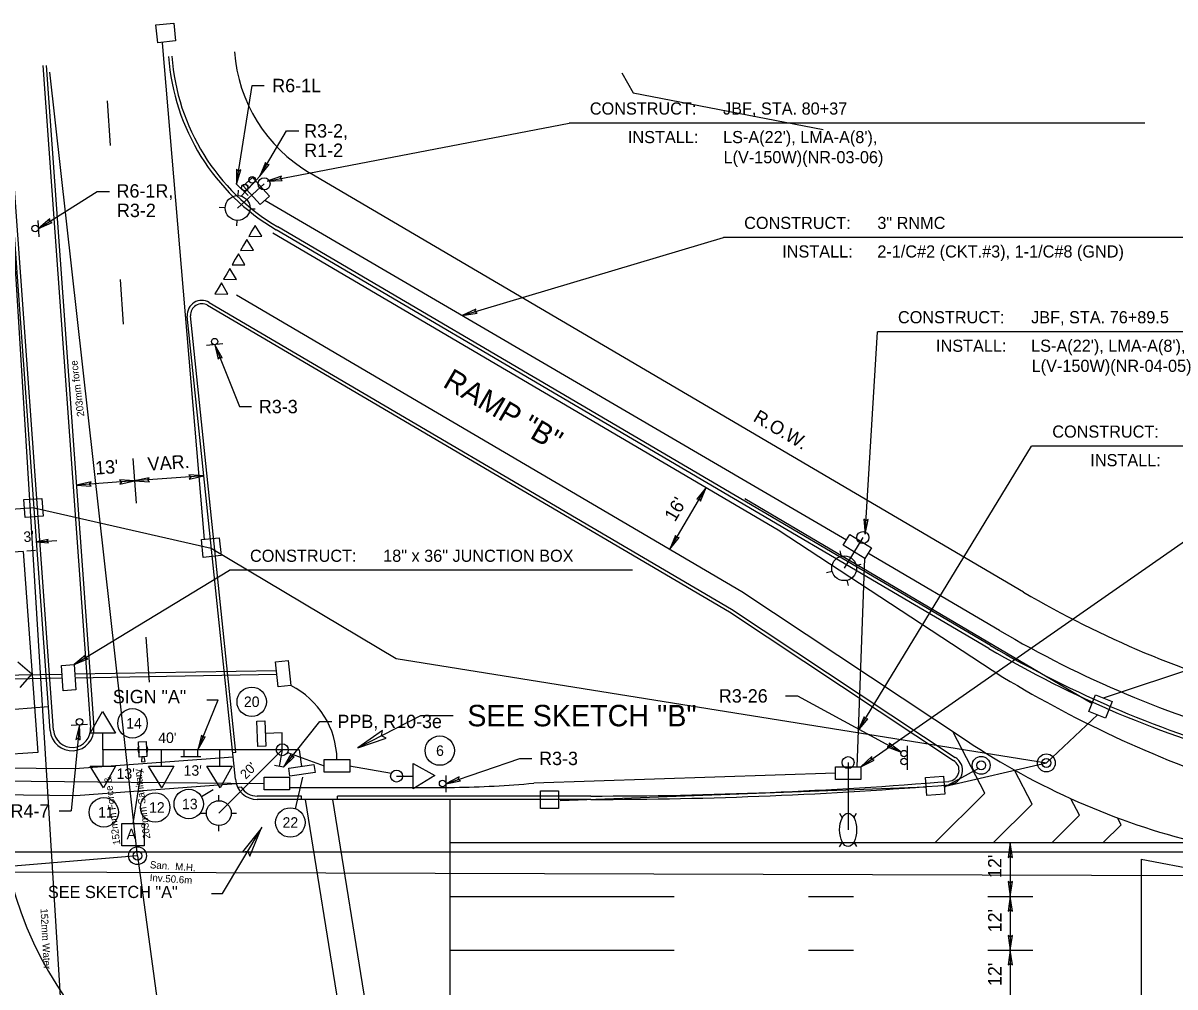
# Model space of a CAD drawing. Extents: x 488740 to 507913, y 466518 to 497949.
# Drawn here: x 503498.7 to 503756.2, y 496091.2 to 496306.6 of the extents above; entities that cross this region are included whole.
import ezdxf

# ---------------------------------------------------------------- set-up
doc = ezdxf.new("R2010")
doc.units = 0
for name, color, linetype in [('1', 7, 'Continuous'), ('10', 7, 'Continuous'), ('12', 7, 'Continuous'), ('23', 7, 'Continuous'), ('32', 7, 'Continuous'), ('36', 7, 'Continuous'), ('38', 7, 'Continuous'), ('42', 7, 'Continuous'), ('6', 7, 'Continuous'), ('8', 7, 'Continuous')]:
    doc.layers.add(name, color=color, linetype=linetype)

msp = doc.modelspace()

# ---------------------------------------------------------------- linework, layer by layer
at = {"layer": '1'}
for p, q in [((503505.55, 496148.6), (503494.86, 496296.48)), ((503503.13, 496297.07), (503513.82, 496149.2)), ((503503.88, 496297.13), (503514.57, 496149.25)), ((503504.8, 496148.54), (503494.11, 496296.42)), ((503722.34, 496179.43), (503562.78, 496273.13)), ((503714.59, 496166.85), (503555.3, 496260.39)), ((503714.97, 496167.5), (503555.68, 496261.04)), ((503539.97, 496243.53), (503656.64, 496175.01)), ((503540.35, 496244.17), (503657.04, 496175.65)), ((503546.19, 496137.67), (503535.44, 496241.12)), ((503546.32, 496143.64), (503536.18, 496241.2)), ((503657.04, 496175.65), (503707.08, 496142.47)), ((503656.64, 496175.01), (503706.67, 496141.85)), ((503546.32, 496143.64), (503545.57, 496143.56)), ((503547.52, 496135.89), (503546.71, 496135.8)), ((503560.96, 496133.88), (503551.07, 496133.88)), ((503625.63, 496133.12), (503551.07, 496133.12)), ((503560.96, 496133.08), (503560.96, 496133.88)), ((503568.97, 496133.08), (503568.97, 496133.88)), ((503625.63, 496133.88), (503568.97, 496133.88))]:
    msp.add_line(p, q, dxfattribs=at)
for points in [[(503528.44, 496306.17), (503532.42, 496306.58), (503532.84, 496302.6), (503528.86, 496302.19)], [(503498.92, 496200.1), (503502.92, 496200.39), (503503.2, 496196.4), (503499.21, 496196.11)], [(503538.6, 496191.16), (503542.58, 496191.57), (503542.99, 496187.59), (503539.01, 496187.18)], [(503736.9, 496152.8), (503738.4, 496156.51), (503742.12, 496155.01), (503740.62, 496151.3)], [(503700.73, 496134.02), (503700.43, 496138.01), (503704.42, 496138.32), (503704.73, 496134.32)], [(503614.38, 496131.07), (503614.38, 496135.07), (503618.38, 496135.07), (503618.38, 496131.07)]]:
    msp.add_lwpolyline(points, close=True, dxfattribs=at)
for centre, radius in [((503712.86, 496140.74), 2), ((503727.42, 496141.28), 2), ((503727.42, 496141.28), 0.999), ((503712.86, 496140.74), 0.999)]:
    msp.add_circle(centre, radius, dxfattribs=at)
for centre, radius, start, end in [((503580.11, 496302.64), 48.99, 184.1335, 239.577), ((503580.11, 496302.64), 48.24, 184.1335, 239.577), ((503580.11, 496302.64), 34.22, 184.1335, 239.5771), ((503538.69, 496241.36), 3.27, 59.577, 184.1335), ((503538.69, 496241.36), 2.51, 59.577, 184.1335), ((503838.63, 496378.08), 230.18, 239.6562, 254.7212), ((503838.63, 496378.08), 244.96, 239.577, 254.7212), ((503838.63, 496378.08), 244.21, 239.577, 254.7212), ((503509.68, 496148.9), 4.9, 184.1335, 4.1335), ((503509.68, 496148.9), 4.15, 184.1335, 4.1335), ((503705.43, 496139.66), 3.27, 274.6874, 59.577), ((503705.4, 496139.68), 2.51, 274.6874, 59.577), ((503551.07, 496138.02), 4.9, 184.1335, 270), ((503625.63, 497112.95), 979.07, 270.00005, 274.68735), ((503551.07, 496138.02), 4.15, 210.9627, 270), ((503625.63, 497112.95), 979.83, 270.00005, 274.68735)]:
    msp.add_arc(centre, radius, start, end, dxfattribs=at)
at = {"layer": '10'}
for p, q in [((503510.13, 496163.26), (503544.84, 496184.32)), ((503634.96, 496184.32), (503544.84, 496184.32)), ((503573.57, 496144.65), (503587.66, 496151.85)), ((503587.66, 496151.85), (503594.84, 496151.85))]:
    msp.add_line(p, q, dxfattribs=at)
for points in [[(503510.13, 496163.26), (503513.2, 496164.57), (503512.65, 496164.79), (503512.71, 496165.38)], [(503573.57, 496144.65), (503579.89, 496146.82), (503578.83, 496147.34), (503579.03, 496148.5)]]:
    msp.add_lwpolyline(points, close=True, dxfattribs=at)
at = {"layer": '12'}
for p, q in [((503553.31, 496271.28), (503620.8, 496284.24)), ((503749.42, 496284.24), (503620.8, 496284.24)), ((503596.89, 496241.24), (503655.28, 496258.68)), ((503783.91, 496258.68), (503655.28, 496258.68)), ((503686.92, 496192.41), (503689.65, 496237.62)), ((503818.28, 496237.62), (503689.65, 496237.62)), ((503685.37, 496148.52), (503724.14, 496212.06)), ((503852.76, 496212.06), (503724.14, 496212.06)), ((503685.96, 496140.4), (503758.51, 496190.99)), ((503543.3, 496112.11), (503552.14, 496126.95)), ((503748.62, 496119.8), (503767.1, 496116.23)), ((503540.82, 496112.11), (503543.3, 496112.11))]:
    msp.add_line(p, q, dxfattribs=at)
for points in [[(503553.31, 496271.28), (503556.65, 496271.44), (503556.21, 496271.84), (503556.47, 496272.37)], [(503596.89, 496241.24), (503600.2, 496241.73), (503599.72, 496242.08), (503599.93, 496242.64)], [(503686.92, 496192.41), (503687.59, 496195.69), (503687.1, 496195.36), (503686.65, 496195.74)], [(503685.37, 496148.52), (503687.49, 496151.1), (503686.91, 496151.04), (503686.69, 496151.59)], [(503685.96, 496140.4), (503688.94, 496141.91), (503688.38, 496142.09), (503688.4, 496142.68)], [(503551.97, 496126.6), (503547.77, 496121.4), (503548.95, 496121.53), (503549.4, 496120.43)]]:
    msp.add_lwpolyline(points, close=True, dxfattribs=at)
msp.add_lwpolyline([(503748.62, 496119.8), (503748.62, 496070.41), (503748.62, 495995.75)], dxfattribs=at)
at = {"layer": '23'}
for p, q in [((503539.25, 496191.18), (503529.88, 496302.17)), ((503524.39, 495809.94), (503494.31, 496296.44)), ((503524.31, 496120.55), (503504.75, 496295.61)), ((503632.55, 496295.45), (503635.11, 496291.01)), ((503635.11, 496291.01), (503677.55, 496282.8)), ((503660.06, 496200.34), (503737.56, 496154.62)), ((503501.21, 496198.3), (503462.11, 496195.47)), ((503501.21, 496198.3), (503540.8, 496189.26)), ((503540.76, 496189.27), (503582.14, 496164.63)), ((503740.21, 496155.84), (503781.2, 496169.5)), ((503582.14, 496164.63), (503727.42, 496141.28)), ((503727.42, 496141.28), (503738.89, 496152.04)), ((503704.62, 496135.86), (503712.36, 496140.14)), ((503704.86, 496136.06), (503727.42, 496141.28)), ((503618.76, 496132.9), (503700.59, 496135.96)), ((503524.31, 496120.55), (503402.79, 496110.21)), ((503524.31, 496120.55), (503546.14, 495959.54)), ((503398.08, 496117.2), (503762.28, 496116.11))]:
    msp.add_line(p, q, dxfattribs=at)
for radius in [2, 0.999]:
    msp.add_circle((503524.31, 496120.55), radius, dxfattribs=at)
at = {"layer": '32'}
for p, q in [((503501.75, 496190.65), (503506.31, 496190.98)), ((503498.76, 496188.54), (503480.78, 496187.24)), ((503498.76, 496188.54), (503502.01, 496143.63)), ((503501.53, 496188.74), (503499.55, 496188.59)), ((503537.77, 496144.23), (503542.32, 496155.34)), ((503539.84, 496155.34), (503542.32, 496155.34)), ((503516.59, 496144.23), (503516.59, 496147.89)), ((503556.66, 496148.01), (503552.88, 496147.84)), ((503556.66, 496144.23), (503556.66, 496148.01)), ((503502.01, 496143.63), (503484.03, 496142.33)), ((503556.66, 496144.23), (503516.59, 496144.23)), ((503516.59, 496144.23), (503516.59, 496140.57)), ((503529.61, 496144.23), (503529.61, 496140.57)), ((503533.98, 496142.71), (503538.49, 496142.71)), ((503534.74, 496142.71), (503534.74, 496144.23)), ((503537.77, 496142.71), (503537.77, 496144.23)), ((503542.63, 496144.23), (503542.63, 496140.57)), ((503556.66, 496144.23), (503555.98, 496140.51)), ((503560.41, 496144.23), (503556.66, 496144.23)), ((503560.41, 496144.23), (503560.94, 496140.49)), ((503556.91, 496140.34), (503554.94, 496140.7)), ((503559.63, 496131.04), (503561.24, 496138.12)), ((503582.22, 496138.35), (503585.88, 496138.35)), ((503538.59, 496133.77), (503541.23, 496135.34))]:
    msp.add_line(p, q, dxfattribs=at)
for points in [[(503501.75, 496190.65), (503504.42, 496190.46), (503504.11, 496190.82), (503504.37, 496191.22)], [(503513.76, 496147.89), (503516.47, 496152.73), (503519.43, 496147.89)], [(503553.01, 496145), (503551.24, 496144.92), (503550.98, 496150.59), (503552.75, 496150.67)], [(503537.77, 496144.23), (503539.46, 496147.11), (503538.89, 496146.96), (503538.58, 496147.47)], [(503519.43, 496140.57), (503516.71, 496135.72), (503513.76, 496140.57)], [(503532.45, 496140.57), (503529.73, 496135.72), (503526.78, 496140.57)], [(503545.47, 496140.57), (503542.75, 496135.72), (503539.8, 496140.57)], [(503563.74, 496140.89), (503563.99, 496139.13), (503558.38, 496138.33), (503558.13, 496140.09)], [(503585.88, 496141.18), (503590.73, 496138.47), (503585.88, 496135.52)]]:
    msp.add_lwpolyline(points, close=True, dxfattribs=at)
for centre, radius in [((503552.61, 496270.66), 1.34), ((503686.41, 496191.63), 1.34), ((503549.84, 496154.94), 3.29), ((503523.19, 496150.12), 3.29), ((503591.86, 496144.03), 3.29), ((503556.66, 496144.23), 1.34), ((503683.12, 496141.35), 1.34), ((503582.22, 496138.35), 1.34), ((503528.27, 496131.33), 3.29), ((503535.76, 496132.1), 3.29), ((503516.77, 496130.24), 3.29), ((503558.46, 496127.97), 3.29)]:
    msp.add_circle(centre, radius, dxfattribs=at)
at = {"layer": '36'}
for p, q in [((503517.51, 496289.22), (503518.23, 496279.23)), ((503554.52, 496259.71), (503667.46, 496193.39)), ((503520.4, 496249.26), (503521.12, 496239.27)), ((503546.4, 496245.89), (503659.34, 496179.57)), ((503523.28, 496209.3), (503524.01, 496199.31)), ((503667.46, 496193.39), (503717.71, 496160.47)), ((503659.34, 496179.57), (503709.59, 496146.26)), ((503526.17, 496169.34), (503526.89, 496159.35)), ((503497.59, 496163.89), (503500.67, 496161.22)), ((503500.67, 496161.22), (503498, 496158.13)), ((503457, 496150.43), (503504.41, 496153.85)), ((503713.65, 496134.55), (503706.49, 496148.31)), ((503510.32, 496140.01), (503545.67, 496142.65)), ((503447.68, 496140.72), (503510.32, 496140.01)), ((503724.24, 496132.09), (503720.29, 496139.69)), ((503435.97, 496134.84), (503510.51, 496134)), ((503510.51, 496134), (503546.36, 496136.68)), ((503702.57, 496123.48), (503713.65, 496134.55)), ((503581.59, 496010.27), (503561.88, 496133.12)), ((503587.77, 496009.65), (503567.97, 496133.08)), ((503594.18, 496071.42), (503594.17, 496133.12)), ((503715.63, 496123.48), (503724.24, 496132.09)), ((503734.84, 496129.63), (503732.93, 496133.29)), ((503728.69, 496123.48), (503734.84, 496129.63)), ((503740.13, 496123.48), (503744.12, 496127.47)), ((503744.12, 496127.47), (503743.32, 496129.02)), ((503594.17, 496123.48), (503761.31, 496123.48)), ((503594.17, 496111.46), (503644.25, 496111.46)), ((503674.3, 496111.46), (503684.32, 496111.46)), ((503714.37, 496111.46), (503724.38, 496111.46)), ((503594.17, 496099.44), (503644.25, 496099.44)), ((503674.3, 496099.44), (503684.32, 496099.44)), ((503714.37, 496099.44), (503724.38, 496099.44))]:
    msp.add_line(p, q, dxfattribs=at)
for points in [[(503552.08, 496258.98), (503550.6, 496261.35), (503549.88, 496260.13), (503549.16, 496258.91)], [(503550.22, 496255.82), (503548.74, 496258.2), (503548.02, 496256.97), (503547.31, 496255.75)], [(503548.31, 496252.56), (503546.89, 496255.04), (503546.17, 496253.82), (503545.45, 496252.59)], [(503546.4, 496249.3), (503544.97, 496251.78), (503544.26, 496250.56), (503543.54, 496249.34)], [(503544.48, 496246.04), (503543.06, 496248.52), (503542.34, 496247.3), (503541.62, 496246.08)]]:
    msp.add_lwpolyline(points, close=True, dxfattribs=at)
for centre, radius, start, end in [((503851.62, 496381.27), 258.23, 238.7636, 252.127), ((503800.29, 496282.06), 163.3, 236.2647, 256.1902), ((503575.88, 496135.92), 82.51, 189.6092, 269.9061)]:
    msp.add_arc(centre, radius, start, end, dxfattribs=at)
at = {"layer": '38'}
for p, q in [((503523.65, 496204.3), (503510.66, 496203.37)), ((503539.15, 496205.42), (503523.65, 496204.3)), ((503643.26, 496189.01), (503651.37, 496202.83)), ((503719.37, 496123.48), (503719.37, 496111.46)), ((503719.37, 496111.46), (503719.37, 496099.44)), ((503719.37, 496099.44), (503719.37, 496087.42))]:
    msp.add_line(p, q, dxfattribs=at)
for points in [[(503510.66, 496203.37), (503513.99, 496203.13), (503513.6, 496203.58), (503513.92, 496204.08)], [(503523.65, 496204.3), (503520.31, 496204.54), (503520.7, 496204.09), (503520.38, 496203.59)], [(503523.65, 496204.3), (503526.98, 496204.07), (503526.59, 496204.52), (503526.91, 496205.01)], [(503539.15, 496205.42), (503535.81, 496205.66), (503536.2, 496205.21), (503535.88, 496204.71)], [(503651.37, 496202.83), (503649.29, 496200.22), (503649.88, 496200.29), (503650.11, 496199.74)], [(503643.26, 496189.01), (503645.34, 496191.63), (503644.75, 496191.56), (503644.52, 496192.11)], [(503719.37, 496123.48), (503718.9, 496120.17), (503719.37, 496120.53), (503719.85, 496120.17)], [(503719.37, 496111.46), (503719.85, 496114.77), (503719.37, 496114.41), (503718.9, 496114.77)], [(503719.37, 496111.46), (503718.9, 496108.15), (503719.37, 496108.51), (503719.85, 496108.15)], [(503719.37, 496099.44), (503719.85, 496102.75), (503719.37, 496102.39), (503718.9, 496102.75)], [(503719.37, 496099.44), (503718.9, 496096.13), (503719.37, 496096.49), (503719.85, 496096.13)]]:
    msp.add_lwpolyline(points, close=True, dxfattribs=at)
at = {"layer": '42'}
for p, q in [((503546.4, 496270.6), (503549.94, 496292.63)), ((503549.94, 496292.63), (503552.65, 496292.63)), ((503551.68, 496272.36), (503557.62, 496282.51)), ((503557.62, 496282.51), (503560.33, 496282.51)), ((503551.68, 496272.36), (503549.16, 496269.71)), ((503502.16, 496260.66), (503515.33, 496268.95)), ((503515.33, 496268.95), (503518.04, 496268.95)), ((503549.06, 496268.08), (503546.4, 496270.6)), ((503550.04, 496270.64), (503547.52, 496267.98)), ((503502.03, 496262.5), (503502.29, 496258.84)), ((503543.39, 496234.89), (503539.75, 496234.51)), ((503541.58, 496234.7), (503547.1, 496220.9)), ((503547.1, 496220.9), (503549.81, 496220.9)), ((503669.13, 496156.25), (503671.84, 496156.25)), ((503671.84, 496156.25), (503694.95, 496143.71)), ((503511.34, 496149.76), (503509.48, 496130.54)), ((503513.15, 496149.89), (503509.5, 496149.63)), ((503556.91, 496140.34), (503565.06, 496150.57)), ((503565.06, 496150.57), (503567.77, 496150.57)), ((503696.32, 496145.13), (503696.32, 496141.47)), ((503593.2, 496136.62), (503609.74, 496142.29)), ((503609.74, 496142.29), (503612.45, 496142.29)), ((503696.33, 496143.36), (503696.33, 496139.7)), ((503593.2, 496138.44), (503593.2, 496134.78)), ((503506.77, 496130.54), (503509.48, 496130.54))]:
    msp.add_line(p, q, dxfattribs=at)
for points in [[(503546.4, 496270.6), (503547.39, 496273.79), (503546.87, 496273.52), (503546.46, 496273.94)], [(503551.68, 496272.36), (503553.76, 496274.98), (503553.17, 496274.91), (503552.94, 496275.46)], [(503502.16, 496260.66), (503505.21, 496262.02), (503504.66, 496262.23), (503504.71, 496262.82)], [(503541.58, 496234.7), (503542.37, 496231.45), (503542.68, 496231.96), (503543.25, 496231.81)], [(503511.34, 496149.76), (503510.55, 496146.51), (503511.05, 496146.82), (503511.49, 496146.42)], [(503694.95, 496143.71), (503692.27, 496145.7), (503692.35, 496145.12), (503691.82, 496144.87)], [(503556.91, 496140.34), (503559.34, 496142.63), (503558.75, 496142.65), (503558.6, 496143.22)], [(503593.2, 496136.62), (503596.48, 496137.24), (503595.99, 496137.57), (503596.17, 496138.14)]]:
    msp.add_lwpolyline(points, close=True, dxfattribs=at)
for centre in [(503549.94, 496271.56), (503548.26, 496269.82), (503548.31, 496269.84), (503501.45, 496260.68), (503541.56, 496235.41), (503511.34, 496150.47), (503695.61, 496143.36), (503695.62, 496141.59), (503592.49, 496136.67)]:
    msp.add_circle(centre, 0.721, dxfattribs=at)
at = {"layer": '6'}
for p, q in [((503552.77, 496266.99), (503682.77, 496191.11)), ((503686.8, 496186.93), (503685.07, 496140.4)), ((503716.95, 496170.87), (503687.55, 496188.14)), ((503458.16, 496159.43), (503507.49, 496160.27)), ((503458.46, 496160.29), (503507.42, 496161.13)), ((503510.28, 496161.18), (503555.38, 496161.95)), ((503510.34, 496160.32), (503555.47, 496161.09)), ((503524.68, 496143.52), (503524.61, 496145.01)), ((503526.31, 496145.1), (503526.38, 496143.6)), ((503557.85, 496143.62), (503566.06, 496140.66)), ((503523.36, 496127.74), (503525.31, 496139.94)), ((503571.72, 496140.66), (503581.04, 496138.98)), ((503432.95, 496137.91), (503552.64, 496136.71)), ((503680.29, 496138.99), (503612.88, 496136.77)), ((503558.31, 496135.82), (503595.13, 496135.82)), ((503520.84, 496122.78), (503520.84, 496127.74)), ((503520.84, 496127.74), (503525.8, 496127.74)), ((503525.8, 496127.74), (503525.8, 496122.78)), ((503438.74, 496121.4), (503760.91, 496121.4)), ((503525.8, 496122.78), (503520.84, 496122.78))]:
    msp.add_line(p, q, dxfattribs=at)
for points in [[(503551.74, 496266.02), (503547.91, 496270.19), (503550, 496272.11), (503553.83, 496267.93)], [(503686.82, 496186.92), (503682.01, 496189.92), (503683.5, 496192.32), (503688.32, 496189.33)], [(503510.13, 496163.26), (503510.53, 496157.61), (503507.71, 496157.4), (503507.3, 496163.06)], [(503558, 496164.19), (503558.59, 496158.55), (503555.77, 496158.25), (503555.18, 496163.89)], [(503524.72, 496142.59), (503524.56, 496146), (503526.26, 496146.08), (503526.42, 496142.68)], [(503525.29, 496142.62), (503525.19, 496141.55), (503526.02, 496141.6), (503525.82, 496142.65)], [(503566.06, 496142.07), (503571.73, 496142.07), (503571.73, 496139.23), (503566.06, 496139.23)], [(503685.96, 496137.57), (503680.29, 496137.57), (503680.29, 496140.4), (503685.96, 496140.4)], [(503552.64, 496138.12), (503558.31, 496138.12), (503558.31, 496135.29), (503552.64, 496135.29)]]:
    msp.add_lwpolyline(points, close=True, dxfattribs=at)
for centre, radius, start, end in [((503838.63, 496378.08), 240.29, 239.5771, 254.7211), ((503550.12, 496141.8), 18.77, 0.8604, 63.1431), ((503525.49, 496144.31), 1.13, 141.381, 224.1988), ((503525.49, 496144.31), 1.13, 321.3807, 44.2003), ((503592.07, 496358.28), 222.49, 270.7879, 275.3669)]:
    msp.add_arc(centre, radius, start, end, dxfattribs=at)
at = {"layer": '8'}
for p, q in [((503552.61, 496270.66), (503546.69, 496265.26)), ((503546.84, 496268.04), (503546.89, 496269.26)), ((503542.58, 496265.43), (503543.91, 496265.36)), ((503549.46, 496265.11), (503550.62, 496265.06)), ((503546.53, 496261.25), (503546.58, 496262.48)), ((503686.41, 496191.63), (503682.24, 496184.78)), ((503681.61, 496187.49), (503681.32, 496188.69)), ((503678.26, 496183.79), (503679.55, 496184.11)), ((503684.95, 496185.42), (503686.07, 496185.69)), ((503683.21, 496180.89), (503682.92, 496182.09)), ((503556.66, 496144.23), (503542.49, 496130.06)), ((503683.12, 496141.35), (503683.12, 496126.32)), ((503542.51, 496132.84), (503542.51, 496134.07)), ((503538.38, 496130.04), (503539.71, 496130.04)), ((503545.27, 496130.04), (503546.42, 496130.04)), ((503681.21, 496130.04), (503681.78, 496129)), ((503684.43, 496129.03), (503684.99, 496130.04)), ((503542.51, 496126.06), (503542.51, 496127.28)), ((503681.23, 496122.54), (503681.83, 496123.61)), ((503684.43, 496123.59), (503684.99, 496122.6))]:
    msp.add_line(p, q, dxfattribs=at)
for centre in [(503546.69, 496265.26), (503682.24, 496184.78), (503542.49, 496130.06)]:
    msp.add_circle(centre, 2.78, dxfattribs=at)
msp.add_ellipse((503683.12, 496126.32), major_axis=(0.02, -3.75), ratio=0.505309, dxfattribs=at)

# ---------------------------------------------------------------- texts
at = {"layer": '1'}
for s, height, p in [('RAMP "B"', 4.796, (503592.31, 496225.46)), ('R.O.W.', 2.993, (503661.7, 496217.77))]:
    msp.add_text(s, height=height, rotation=329.577, dxfattribs=at).set_placement(p)
at = {"layer": '10'}
for s, height, p in [('CONSTRUCT:', 2.716, (503549.45, 496186.21)), ('18" x 36" JUNCTION BOX                  ', 2.7163, (503579.21, 496186.21)), ('SEE SKETCH "B"', 4.7957, (503598.02, 496149.45))]:
    msp.add_text(s, height=height, dxfattribs=at).set_placement(p)
at = {"layer": '12'}
for s, height, p in [('CONSTRUCT:', 2.716, (503625.4, 496286.13)), ('JBF, STA. 80+37                    ', 2.7163, (503655.17, 496286.13)), ('INSTALL:', 2.716, (503633.91, 496279.75)), ("LS-A(22'), LMA-A(8'),                          ", 2.7163, (503655.17, 496279.75)), ('L(V-150W)(NR-03-06)                            ', 2.7163, (503655.28, 496275.26)), ('CONSTRUCT:', 2.716, (503659.89, 496260.57)), ('3" RNMC                            ', 2.7163, (503689.65, 496260.57)), ('INSTALL:', 2.716, (503668.39, 496254.2)), ('2-1/C#2 (CKT.#3), 1-1/C#8 (GND)                ', 2.7163, (503689.65, 496254.2)), ('CONSTRUCT:', 2.716, (503694.26, 496239.5)), ('JBF, STA. 76+89.5                  ', 2.7163, (503724.02, 496239.5)), ('INSTALL:', 2.716, (503702.76, 496233.13)), ("LS-A(22'), LMA-A(8'),                          ", 2.7163, (503724.02, 496233.13)), ('L(V-150W)(NR-04-05)                           ', 2.7163, (503724.14, 496228.64)), ('CONSTRUCT:', 2.716, (503728.75, 496213.95)), ('INSTALL:', 2.716, (503737.25, 496207.57)), ('SEE SKETCH "A"', 2.7163, (503504.29, 496111.09))]:
    msp.add_text(s, height=height, dxfattribs=at).set_placement(p)
at = {"layer": '23'}
for s, height, rotation, p in [('203mm force', 1.6204, 97.198, (503512.44, 496218.76)), ('203mm Sanitary', 1.6204, 97.6922, (503527.21, 496124.39)), ('152mm Force & ', 1.6204, 97.6922, (503520.49, 496123.08)), ('San.  M.H.', 1.62, 356.0653, (503527.04, 496117.75)), ('Inv.50.6m', 1.62, 356.0653, (503527, 496114.89)), ('152mm Water', 1.6205, 273.0647, (503502.63, 496108.74))]:
    msp.add_text(s, height=height, rotation=rotation, dxfattribs=at).set_placement(p)
at = {"layer": '32'}
msp.add_text("3'", height=2.344, rotation=4.1334, dxfattribs=at).set_placement((503498.91, 496190.6))
for s, height, p in [('SIGN "A"', 2.993, (503518.79, 496154.6)), ('20', 2.344, (503548.09, 496153.77)), ('14', 2.344, (503521.79, 496148.95)), ("40'", 2.344, (503528.94, 496145.73)), ('6', 2.34, (503591.04, 496142.85)), ("13'", 2.344, (503519.64, 496137.72)), ("13'", 2.344, (503534.62, 496138.42)), ('12', 2.344, (503526.9, 496130.16)), ('13', 2.344, (503534.26, 496130.92)), ('11', 2.344, (503515.51, 496129.07)), ('22', 2.344, (503556.73, 496126.8))]:
    msp.add_text(s, height=height, dxfattribs=at).set_placement(p)
at = {"layer": '38'}
for s, rotation, p in [("13'", 4.1333, (503514.95, 496205.68)), ('VAR.', 4.1334, (503526.7, 496206.54)), ("16'", 59.5768, (503644.44, 496194.98)), ("12'", 90, (503717.39, 496115.56)), ("12'", 90, (503717.4, 496103.42)), ("12'", 90, (503717.4, 496091.42))]:
    msp.add_text(s, height=2.993, rotation=rotation, dxfattribs=at).set_placement(p)
at = {"layer": '42'}
for s, height, p in [('R6-1L', 2.993, (503554.42, 496291.13)), ('R3-2,', 2.993, (503561.57, 496281)), ('R1-2', 2.993, (503561.58, 496276.66)), ('R6-1R,', 2.993, (503519.63, 496267.59)), ('R3-2', 2.993, (503519.73, 496263.23)), ('R3-3', 2.993, (503551.44, 496219.4)), ('R3-26', 2.993, (503654.24, 496154.76)), ('PPB, R10-3e', 2.9928, (503568.99, 496149.05)), ('R3-3', 2.993, (503614.07, 496140.79)), ('R4-7', 2.993, (503495.94, 496129.04))]:
    msp.add_text(s, height=height, dxfattribs=at).set_placement(p)
at = {"layer": '6'}
msp.add_text('A', height=2.34, dxfattribs=at).set_placement((503521.88, 496124.23))
at = {"layer": '8'}
msp.add_text("20'", height=2.109, rotation=45.0006, dxfattribs=at).set_placement((503548.51, 496137.53))

doc.saveas('drawing.dxf')
